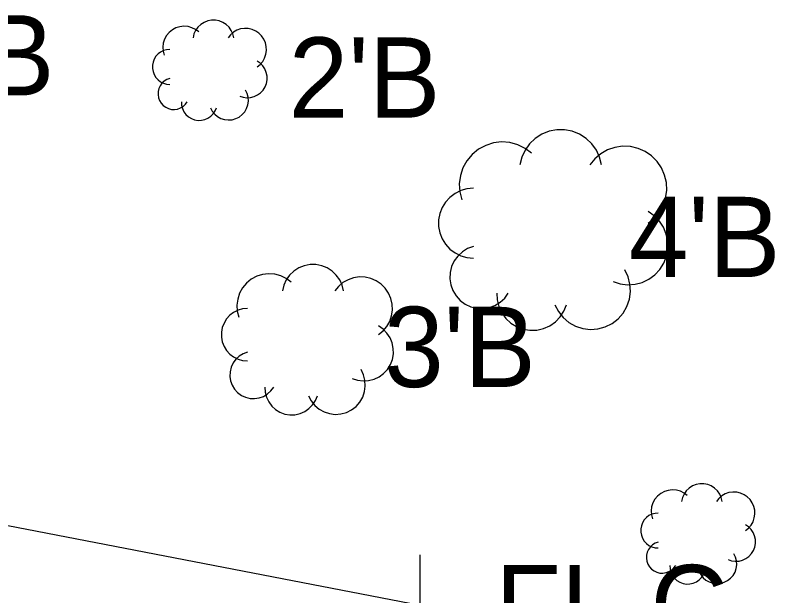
# Model space of a CAD drawing. Extents: x 1363693 to 1365209, y 422201 to 424153.
# Drawn here: x 1364152.05 to 1364167.19, y 423063 to 423074.57 of the extents above; entities that cross this region are included whole.
import ezdxf

# ---------------------------------------------------------------- set-up
doc = ezdxf.new("R2010")
doc.units = 0
for name, color, linetype in [('RD_X_Fence', 7, 'Continuous'), ('SV_X_Shot_Marker', 7, 'Continuous'), ('VG_X_Cells', 7, 'Continuous'), ('VG_X_Text', 7, 'Continuous')]:
    doc.layers.add(name, color=color, linetype=linetype)

msp = doc.modelspace()

# ---------------------------------------------------------------- linework, layer by layer
at = {"layer": 'RD_X_Fence'}
msp.add_line((1364139.117, 423066.868), (1364160.121, 423062.812), dxfattribs=at)
at = {"layer": 'SV_X_Shot_Marker'}
msp.add_line((1364160.121, 423061.812), (1364160.121, 423063.812), dxfattribs=at)
at = {"layer": 'VG_X_Cells'}
for points in [[(1364156.407, 423074.119), (1364156.388, 423074.194), (1364156.356, 423074.265), (1364156.311, 423074.329), (1364156.254, 423074.383), (1364156.189, 423074.425), (1364156.116, 423074.454), (1364156.04, 423074.469), (1364155.961, 423074.469), (1364155.885, 423074.454), (1364155.812, 423074.425), (1364155.747, 423074.383), (1364155.69, 423074.329), (1364155.645, 423074.265), (1364155.612, 423074.194), (1364155.594, 423074.119)], [(1364155.71, 423074.235), (1364155.645, 423074.284), (1364155.572, 423074.319), (1364155.493, 423074.341), (1364155.411, 423074.347), (1364155.33, 423074.337), (1364155.252, 423074.313), (1364155.181, 423074.274), (1364155.117, 423074.223), (1364155.065, 423074.16), (1364155.025, 423074.089), (1364154.999, 423074.012), (1364154.989, 423073.931), (1364154.994, 423073.849), (1364155.014, 423073.77)], [(1364156.871, 423073.538), (1364156.932, 423073.587), (1364156.982, 423073.646), (1364157.021, 423073.714), (1364157.046, 423073.788), (1364157.057, 423073.864), (1364157.054, 423073.942), (1364157.036, 423074.018), (1364157.005, 423074.089), (1364156.961, 423074.154), (1364156.906, 423074.209), (1364156.842, 423074.252), (1364156.771, 423074.284), (1364156.695, 423074.301), (1364156.617, 423074.304), (1364156.54, 423074.293), (1364156.467, 423074.268), (1364156.399, 423074.229), (1364156.34, 423074.179), (1364156.291, 423074.119)], [(1364155.13, 423073.886), (1364155.066, 423073.88), (1364155.004, 423073.863), (1364154.946, 423073.834), (1364154.895, 423073.795), (1364154.852, 423073.748), (1364154.818, 423073.693), (1364154.795, 423073.633), (1364154.783, 423073.57), (1364154.783, 423073.506), (1364154.795, 423073.443), (1364154.818, 423073.383), (1364154.852, 423073.328), (1364154.895, 423073.281), (1364154.946, 423073.242), (1364155.004, 423073.213), (1364155.066, 423073.196), (1364155.13, 423073.19)], [(1364156.523, 423072.957), (1364156.593, 423072.934), (1364156.667, 423072.924), (1364156.741, 423072.929), (1364156.813, 423072.947), (1364156.88, 423072.979), (1364156.939, 423073.023), (1364156.99, 423073.077), (1364157.029, 423073.14), (1364157.056, 423073.209), (1364157.069, 423073.282), (1364157.068, 423073.356), (1364157.053, 423073.429), (1364157.025, 423073.497), (1364156.984, 423073.559), (1364156.932, 423073.612), (1364156.871, 423073.654)], [(1364155.13, 423073.306), (1364155.072, 423073.285), (1364155.019, 423073.253), (1364154.974, 423073.211), (1364154.938, 423073.161), (1364154.912, 423073.106), (1364154.897, 423073.046), (1364154.895, 423072.985), (1364154.904, 423072.924), (1364154.925, 423072.866), (1364154.957, 423072.814), (1364154.999, 423072.768), (1364155.048, 423072.732), (1364155.104, 423072.706), (1364155.164, 423072.691), (1364155.225, 423072.688), (1364155.286, 423072.698), (1364155.344, 423072.719), (1364155.396, 423072.75), (1364155.442, 423072.792), (1364155.478, 423072.841)], [(1364155.942, 423072.725), (1364155.977, 423072.658), (1364156.025, 423072.598), (1364156.082, 423072.549), (1364156.149, 423072.512), (1364156.221, 423072.489), (1364156.296, 423072.48), (1364156.372, 423072.485), (1364156.445, 423072.506), (1364156.513, 423072.539), (1364156.573, 423072.586), (1364156.623, 423072.643), (1364156.661, 423072.709), (1364156.686, 423072.781), (1364156.696, 423072.856), (1364156.691, 423072.932), (1364156.672, 423073.005), (1364156.639, 423073.074)], [(1364155.362, 423072.841), (1364155.366, 423072.773), (1364155.383, 423072.707), (1364155.412, 423072.645), (1364155.452, 423072.589), (1364155.503, 423072.543), (1364155.561, 423072.507), (1364155.625, 423072.483), (1364155.693, 423072.472), (1364155.762, 423072.474), (1364155.828, 423072.489), (1364155.891, 423072.516), (1364155.947, 423072.555), (1364155.995, 423072.604), (1364156.033, 423072.662), (1364156.059, 423072.725)], [(1364163.738, 423071.584), (1364163.701, 423071.736), (1364163.636, 423071.878), (1364163.546, 423072.005), (1364163.433, 423072.113), (1364163.301, 423072.198), (1364163.156, 423072.256), (1364163.003, 423072.285), (1364162.847, 423072.285), (1364162.693, 423072.256), (1364162.549, 423072.198), (1364162.417, 423072.113), (1364162.304, 423072.005), (1364162.214, 423071.878), (1364162.149, 423071.736), (1364162.112, 423071.584)], [(1364162.344, 423071.816), (1364162.214, 423071.914), (1364162.067, 423071.986), (1364161.91, 423072.028), (1364161.747, 423072.041), (1364161.585, 423072.022), (1364161.429, 423071.973), (1364161.285, 423071.896), (1364161.159, 423071.793), (1364161.054, 423071.668), (1364160.974, 423071.525), (1364160.923, 423071.37), (1364160.901, 423071.209), (1364160.911, 423071.046), (1364160.951, 423070.887)], [(1364164.667, 423070.423), (1364164.787, 423070.521), (1364164.888, 423070.64), (1364164.965, 423070.775), (1364165.016, 423070.922), (1364165.038, 423071.076), (1364165.032, 423071.231), (1364164.997, 423071.383), (1364164.934, 423071.526), (1364164.847, 423071.654), (1364164.737, 423071.764), (1364164.608, 423071.852), (1364164.466, 423071.914), (1364164.314, 423071.949), (1364164.158, 423071.956), (1364164.004, 423071.933), (1364163.857, 423071.883), (1364163.722, 423071.806), (1364163.603, 423071.705), (1364163.505, 423071.584)], [(1364161.183, 423071.12), (1364161.055, 423071.108), (1364160.932, 423071.073), (1364160.817, 423071.015), (1364160.714, 423070.938), (1364160.627, 423070.843), (1364160.56, 423070.734), (1364160.513, 423070.614), (1364160.49, 423070.487), (1364160.49, 423070.359), (1364160.513, 423070.232), (1364160.56, 423070.112), (1364160.627, 423070.003), (1364160.714, 423069.908), (1364160.817, 423069.831), (1364160.932, 423069.773), (1364161.055, 423069.738), (1364161.183, 423069.726)], [(1364163.97, 423069.262), (1364164.111, 423069.215), (1364164.258, 423069.196), (1364164.406, 423069.205), (1364164.549, 423069.242), (1364164.683, 423069.305), (1364164.803, 423069.392), (1364164.904, 423069.501), (1364164.982, 423069.626), (1364165.036, 423069.765), (1364165.062, 423069.911), (1364165.06, 423070.059), (1364165.03, 423070.204), (1364164.974, 423070.341), (1364164.892, 423070.465), (1364164.788, 423070.571), (1364164.667, 423070.655)], [(1364161.183, 423069.959), (1364161.068, 423069.916), (1364160.963, 423069.852), (1364160.872, 423069.769), (1364160.8, 423069.67), (1364160.748, 423069.558), (1364160.719, 423069.439), (1364160.714, 423069.316), (1364160.732, 423069.195), (1364160.774, 423069.079), (1364160.838, 423068.974), (1364160.921, 423068.883), (1364161.02, 423068.811), (1364161.132, 423068.759), (1364161.251, 423068.729), (1364161.374, 423068.724), (1364161.495, 423068.742), (1364161.611, 423068.784), (1364161.716, 423068.848), (1364161.807, 423068.931), (1364161.88, 423069.03)], [(1364158.594, 423069.072), (1364158.567, 423069.186), (1364158.518, 423069.293), (1364158.45, 423069.388), (1364158.366, 423069.469), (1364158.267, 423069.532), (1364158.158, 423069.576), (1364158.043, 423069.598), (1364157.926, 423069.598), (1364157.811, 423069.576), (1364157.702, 423069.532), (1364157.604, 423069.469), (1364157.519, 423069.388), (1364157.451, 423069.293), (1364157.403, 423069.186), (1364157.375, 423069.072)], [(1364157.549, 423069.246), (1364157.451, 423069.32), (1364157.341, 423069.374), (1364157.223, 423069.406), (1364157.101, 423069.415), (1364156.979, 423069.401), (1364156.863, 423069.364), (1364156.755, 423069.306), (1364156.66, 423069.229), (1364156.581, 423069.135), (1364156.521, 423069.028), (1364156.483, 423068.912), (1364156.467, 423068.791), (1364156.474, 423068.668), (1364156.504, 423068.55)], [(1364162.809, 423068.798), (1364162.879, 423068.663), (1364162.973, 423068.544), (1364163.089, 423068.446), (1364163.222, 423068.372), (1364163.366, 423068.325), (1364163.517, 423068.306), (1364163.668, 423068.318), (1364163.814, 423068.358), (1364163.95, 423068.426), (1364164.07, 423068.519), (1364164.17, 423068.633), (1364164.246, 423068.765), (1364164.295, 423068.908), (1364164.316, 423069.059), (1364164.306, 423069.21), (1364164.268, 423069.357), (1364164.202, 423069.494)], [(1364159.291, 423068.202), (1364159.382, 423068.275), (1364159.457, 423068.364), (1364159.515, 423068.465), (1364159.553, 423068.576), (1364159.57, 423068.691), (1364159.565, 423068.808), (1364159.539, 423068.922), (1364159.492, 423069.028), (1364159.426, 423069.125), (1364159.343, 423069.207), (1364159.247, 423069.273), (1364159.14, 423069.32), (1364159.026, 423069.346), (1364158.91, 423069.351), (1364158.794, 423069.334), (1364158.684, 423069.296), (1364158.583, 423069.238), (1364158.494, 423069.163), (1364158.42, 423069.072)], [(1364161.648, 423069.03), (1364161.655, 423068.893), (1364161.689, 423068.76), (1364161.748, 423068.636), (1364161.829, 423068.526), (1364161.93, 423068.433), (1364162.046, 423068.361), (1364162.175, 423068.313), (1364162.31, 423068.291), (1364162.447, 423068.294), (1364162.581, 423068.324), (1364162.706, 423068.379), (1364162.819, 423068.458), (1364162.914, 423068.556), (1364162.989, 423068.671), (1364163.041, 423068.798)], [(1364156.679, 423068.724), (1364156.582, 423068.715), (1364156.49, 423068.689), (1364156.403, 423068.646), (1364156.327, 423068.588), (1364156.262, 423068.516), (1364156.211, 423068.434), (1364156.176, 423068.344), (1364156.158, 423068.25), (1364156.158, 423068.153), (1364156.176, 423068.059), (1364156.211, 423067.969), (1364156.262, 423067.887), (1364156.327, 423067.815), (1364156.403, 423067.757), (1364156.49, 423067.714), (1364156.582, 423067.688), (1364156.679, 423067.679)], [(1364158.768, 423067.331), (1364158.874, 423067.296), (1364158.984, 423067.281), (1364159.095, 423067.288), (1364159.203, 423067.315), (1364159.303, 423067.363), (1364159.393, 423067.428), (1364159.469, 423067.51), (1364159.528, 423067.604), (1364159.568, 423067.708), (1364159.588, 423067.817), (1364159.586, 423067.928), (1364159.564, 423068.037), (1364159.521, 423068.14), (1364159.46, 423068.233), (1364159.382, 423068.312), (1364159.291, 423068.376)], [(1364156.679, 423067.853), (1364156.592, 423067.821), (1364156.513, 423067.774), (1364156.445, 423067.711), (1364156.391, 423067.637), (1364156.352, 423067.553), (1364156.33, 423067.464), (1364156.326, 423067.371), (1364156.34, 423067.28), (1364156.372, 423067.194), (1364156.42, 423067.115), (1364156.482, 423067.047), (1364156.556, 423066.992), (1364156.64, 423066.953), (1364156.729, 423066.931), (1364156.821, 423066.927), (1364156.913, 423066.941), (1364156.999, 423066.972), (1364157.078, 423067.02), (1364157.146, 423067.082), (1364157.201, 423067.157)], [(1364157.898, 423066.982), (1364157.95, 423066.881), (1364158.021, 423066.792), (1364158.108, 423066.718), (1364158.207, 423066.663), (1364158.315, 423066.628), (1364158.429, 423066.614), (1364158.542, 423066.623), (1364158.652, 423066.653), (1364158.754, 423066.704), (1364158.844, 423066.773), (1364158.919, 423066.859), (1364158.976, 423066.958), (1364159.012, 423067.066), (1364159.028, 423067.178), (1364159.021, 423067.292), (1364158.992, 423067.402), (1364158.943, 423067.505)], [(1364157.027, 423067.157), (1364157.033, 423067.054), (1364157.058, 423066.954), (1364157.102, 423066.861), (1364157.163, 423066.779), (1364157.238, 423066.709), (1364157.326, 423066.655), (1364157.422, 423066.619), (1364157.524, 423066.602), (1364157.626, 423066.605), (1364157.727, 423066.628), (1364157.821, 423066.669), (1364157.905, 423066.727), (1364157.977, 423066.801), (1364158.033, 423066.887), (1364158.072, 423066.982)], [(1364166.146, 423064.88), (1364166.127, 423064.955), (1364166.095, 423065.026), (1364166.05, 423065.09), (1364165.993, 423065.144), (1364165.928, 423065.186), (1364165.855, 423065.215), (1364165.779, 423065.23), (1364165.7, 423065.23), (1364165.624, 423065.215), (1364165.551, 423065.186), (1364165.486, 423065.144), (1364165.429, 423065.09), (1364165.384, 423065.026), (1364165.351, 423064.955), (1364165.333, 423064.88)], [(1364165.449, 423064.996), (1364165.384, 423065.045), (1364165.311, 423065.08), (1364165.232, 423065.102), (1364165.15, 423065.108), (1364165.069, 423065.098), (1364164.991, 423065.074), (1364164.92, 423065.035), (1364164.856, 423064.984), (1364164.804, 423064.921), (1364164.764, 423064.85), (1364164.738, 423064.773), (1364164.728, 423064.692), (1364164.733, 423064.61), (1364164.753, 423064.531)], [(1364166.61, 423064.299), (1364166.671, 423064.348), (1364166.721, 423064.407), (1364166.76, 423064.475), (1364166.785, 423064.549), (1364166.796, 423064.625), (1364166.793, 423064.703), (1364166.775, 423064.779), (1364166.744, 423064.85), (1364166.7, 423064.915), (1364166.645, 423064.97), (1364166.581, 423065.013), (1364166.51, 423065.045), (1364166.434, 423065.062), (1364166.356, 423065.065), (1364166.279, 423065.054), (1364166.206, 423065.029), (1364166.138, 423064.99), (1364166.079, 423064.94), (1364166.03, 423064.88)], [(1364164.869, 423064.647), (1364164.805, 423064.641), (1364164.743, 423064.624), (1364164.685, 423064.595), (1364164.634, 423064.556), (1364164.591, 423064.509), (1364164.557, 423064.454), (1364164.534, 423064.394), (1364164.522, 423064.331), (1364164.522, 423064.267), (1364164.534, 423064.204), (1364164.557, 423064.144), (1364164.591, 423064.089), (1364164.634, 423064.042), (1364164.685, 423064.003), (1364164.743, 423063.974), (1364164.805, 423063.957), (1364164.869, 423063.951)], [(1364166.262, 423063.718), (1364166.332, 423063.695), (1364166.406, 423063.685), (1364166.48, 423063.69), (1364166.552, 423063.708), (1364166.619, 423063.74), (1364166.678, 423063.784), (1364166.729, 423063.838), (1364166.768, 423063.901), (1364166.795, 423063.97), (1364166.808, 423064.043), (1364166.807, 423064.117), (1364166.792, 423064.19), (1364166.764, 423064.258), (1364166.723, 423064.32), (1364166.671, 423064.373), (1364166.61, 423064.415)], [(1364164.869, 423064.067), (1364164.811, 423064.046), (1364164.758, 423064.014), (1364164.713, 423063.972), (1364164.677, 423063.922), (1364164.651, 423063.867), (1364164.636, 423063.807), (1364164.634, 423063.746), (1364164.643, 423063.685), (1364164.664, 423063.627), (1364164.696, 423063.575), (1364164.738, 423063.529), (1364164.787, 423063.493), (1364164.843, 423063.467), (1364164.903, 423063.452), (1364164.964, 423063.449), (1364165.025, 423063.459), (1364165.083, 423063.48), (1364165.135, 423063.511), (1364165.181, 423063.553), (1364165.217, 423063.602)], [(1364165.681, 423063.486), (1364165.716, 423063.419), (1364165.764, 423063.359), (1364165.821, 423063.31), (1364165.888, 423063.273), (1364165.96, 423063.25), (1364166.035, 423063.241), (1364166.111, 423063.246), (1364166.184, 423063.267), (1364166.252, 423063.3), (1364166.312, 423063.347), (1364166.362, 423063.404), (1364166.4, 423063.47), (1364166.425, 423063.542), (1364166.435, 423063.617), (1364166.43, 423063.693), (1364166.411, 423063.766), (1364166.378, 423063.835)], [(1364165.101, 423063.602), (1364165.105, 423063.534), (1364165.122, 423063.468), (1364165.151, 423063.406), (1364165.191, 423063.35), (1364165.242, 423063.304), (1364165.3, 423063.268), (1364165.364, 423063.244), (1364165.432, 423063.233), (1364165.501, 423063.235), (1364165.567, 423063.25), (1364165.63, 423063.277), (1364165.686, 423063.316), (1364165.734, 423063.365), (1364165.772, 423063.423), (1364165.798, 423063.486)]]:
    msp.add_lwpolyline(points, dxfattribs=at)

# ---------------------------------------------------------------- texts
at = {"layer": 'SV_X_Shot_Marker'}
msp.add_text('FL C', height=1.6, dxfattribs=at).set_placement((1364161.621, 423062.012))
at = {"layer": 'VG_X_Text'}
for s, p in [("4'B", (1364149.804, 423072.968)), ("2'B", (1364157.5, 423072.525)), ("4'B", (1364164.281, 423069.349)), ("3'B", (1364159.402, 423067.158))]:
    msp.add_text(s, height=1.6, dxfattribs=at).set_placement(p)

doc.saveas('drawing.dxf')
